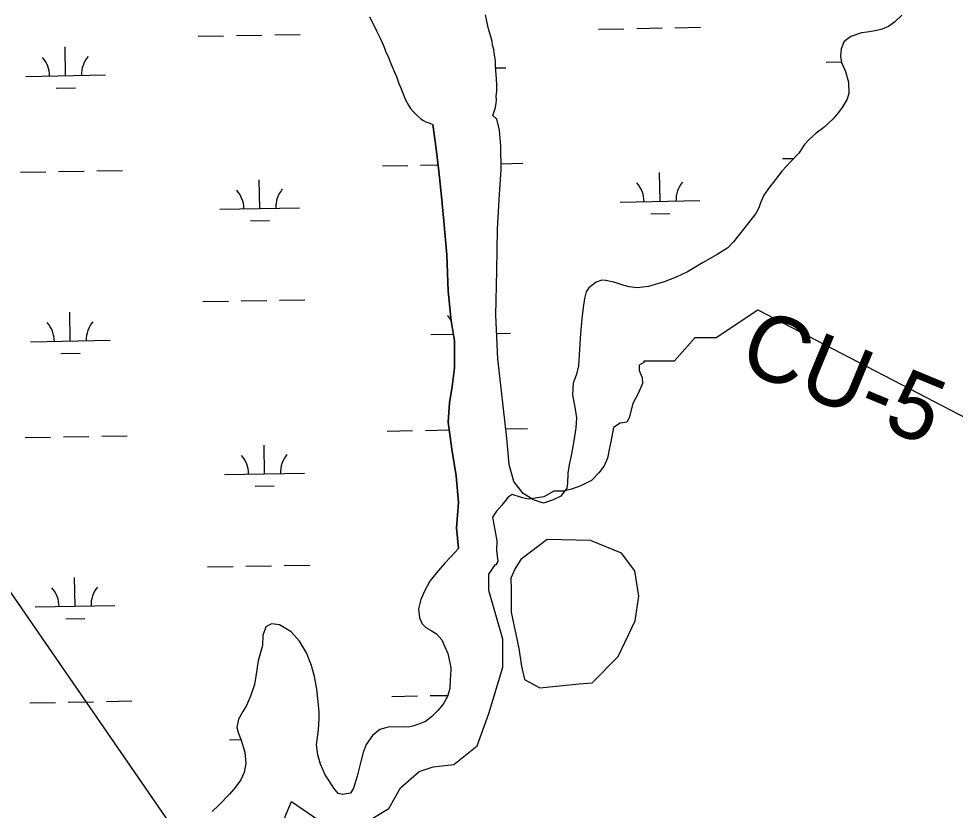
# Model space of a CAD drawing. Extents: x 3914892 to 3953151, y 242587 to 268572.
# Drawn here: x 3940652 to 3941826, y 261355 to 262347 of the extents above; entities that cross this region are included whole.
import ezdxf

# ---------------------------------------------------------------- set-up
doc = ezdxf.new("R2010")
doc.units = 0
for name, color, linetype in [('V-RIVR-EDGE', 7, 'Continuous'), ('V-RIVR-RANG-IDEN', 7, 'Continuous'), ('V-TOPO-SHOR', 7, 'Continuous'), ('V-UTIL-LINE', 7, 'Continuous'), ('V-WETL-SWMP', 7, 'Continuous')]:
    doc.layers.add(name, color=color, linetype=linetype)

msp = doc.modelspace()

# ---------------------------------------------------------------- linework, layer by layer
at = {"layer": 'V-RIVR-EDGE'}
for points in [[(3941436.263321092, 261915.74149882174), (3941436.4269929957, 261918.19657738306), (3941474.2483207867, 261918.19657738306), (3941500.432316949, 261947.2899064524), (3941526.6163131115, 261947.2899064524), (3941578.9843054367, 261982.20190133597), (3943106.3840815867, 261187.95401773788)], [(3941436.0536937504, 261915.87408265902), (3941430.2715205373, 261912.7606047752), (3941430.2715205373, 261906.0888664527), (3941433.8297809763, 261897.19321535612), (3941434.274563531, 261889.6319119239), (3941428.937172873, 261877.17800038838), (3941422.2654345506, 261864.72408885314), (3941417.3728264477, 261846.48800410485), (3941414.7041311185, 261841.15061344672), (3941406.2532625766, 261839.81626578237), (3941397.8023940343, 261834.47887512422), (3941394.688916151, 261816.68757293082), (3941392.9097859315, 261809.12626949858), (3941390.2410906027, 261796.22757540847), (3941386.238047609, 261786.44235920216), (3941379.5663092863, 261777.54670810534), (3941370.225875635, 261768.20627445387), (3941356.88239899, 261761.5345361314), (3941345.3180525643, 261757.08671058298), (3941335.088053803, 261754.8627978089), (3941323.0789248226, 261754.8627978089), (3941310.6250132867, 261747.74627693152), (3941291.4993634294, 261744.63279904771), (3941283.938059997, 261746.41192926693), (3941271.0393659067, 261750.41497226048), (3941265.7019752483, 261747.30149437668), (3941257.6958892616, 261737.0714956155), (3941251.024150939, 261729.51019218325), (3941246.1315428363, 261721.94888875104), (3941251.468933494, 261692.59324013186), (3941251.024150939, 261680.58411115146), (3941252.8032811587, 261666.35106939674), (3941250.5793683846, 261662.3480264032)], [(3941274.787833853, 261657.80073764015), (3941269.083354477, 261645.67871896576), (3941269.796414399, 261631.41752052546), (3941269.796414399, 261602.89512364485), (3941279.066193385, 261557.25928863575), (3941282.631492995, 261535.15443105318), (3941286.1967926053, 261518.75405284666), (3941305.4494105, 261508.0581540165), (3941354.6505451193, 261513.0495734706), (3941371.0509233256, 261514.47569331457), (3941403.8516797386, 261547.27644972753), (3941425.243477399, 261592.19922481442), (3941429.5218369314, 261622.8608014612), (3941424.530417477, 261654.948497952), (3941408.1300392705, 261677.05335553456), (3941368.91174356, 261692.74067381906), (3941314.7191894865, 261694.16679366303), (3941281.9184330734, 261669.2096963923), (3941274.787833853, 261657.75617139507)], [(3940970.9337278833, 261310.14599983), (3940994.2083911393, 261365.42332506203), (3941058.213715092, 261321.78333145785), (3941116.400373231, 261356.69532634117), (3941130.9470377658, 261382.8793225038), (3941154.2217010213, 261403.24465285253), (3941171.6776984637, 261409.06331866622), (3941197.861694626, 261411.9726515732), (3941226.9550236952, 261435.24731482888), (3941241.5016882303, 261475.97797552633), (3941258.9576856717, 261534.16463366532), (3941258.9576856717, 261569.07662854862), (3941241.5016882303, 261630.1726195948), (3941241.5016882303, 261650.5379499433), (3941250.098011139, 261662.81841124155)]]:
    msp.add_lwpolyline(points, dxfattribs=at)
at = {"layer": 'V-TOPO-SHOR'}
for points in [[(3941310.292, 261739.66199999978), (3941297.703, 261744.04499999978), (3941284.72, 261751.65299999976), (3941272.8030000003, 261766.86199999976), (3941267.128, 261788.25099999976), (3941263.98, 261821.34699999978), (3941252.9110000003, 261920.84199999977), (3941250.302, 261975.29299999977), (3941251.676, 262031.51199999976), (3941252.415, 262083.11999999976), (3941254.801, 262126.95699999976), (3941256.88, 262157.54999999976), (3941256.5500000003, 262187.51299999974), (3941254.983, 262207.4379999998), (3941251.754, 262221.3579999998), (3941246.644, 262225.722)], [(3941203.759, 261682.87499999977), (3941201.1580000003, 261708.69999999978), (3941203.454, 261740.65299999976), (3941200.566, 261774.02999999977), (3941195.251, 261807.31199999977), (3941190.715, 261841.43499999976), (3941192.228, 261865.52599999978), (3941195.505, 261885.90399999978), (3941198.389, 261909.50899999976), (3941198.727, 261943.27599999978), (3941194.268, 261968.22099999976), (3941190.418, 262005.61099999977), (3941188.9560000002, 262051.19399999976), (3941185.19, 262093.44599999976), (3941182.404, 262124.12499999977), (3941179.037, 262155.8629999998), (3941175.535, 262184.08399999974), (3941171.576, 262214.5849999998)]]:
    msp.add_lwpolyline(points, dxfattribs=at)
at = {"layer": 'V-UTIL-LINE'}
msp.add_lwpolyline([(3937257.69907959, 266529.8389520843), (3940896.284, 261258.97), (3942305.4820000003, 257189.557), (3945242.894, 251786.949), (3947661.3890917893, 248530.41995604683)], dxfattribs=at)
at = {"layer": 'V-WETL-SWMP'}
for p, q in [((3941238.685, 262346.326), (3941237.545, 262352.113)), ((3941759.256, 262351.529), (3941750.111, 262342.77400000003)), ((3941240.225, 262338.099), (3941238.685, 262346.326)), ((3941241.649, 262332.93700000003), (3941240.225, 262338.099)), ((3941742.523, 262337.288), (3941734.548, 262333.928)), ((3941750.111, 262342.77400000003), (3941742.523, 262337.288)), ((3940877.150642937, 262325.0964673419), (3940909.145522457, 262325.668904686)), ((3940925.142962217, 262325.9551233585), (3940957.137841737, 262326.52756070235)), ((3940973.135281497, 262326.8137793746), (3941005.1301610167, 262327.3862167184)), ((3941244.108, 262324.745), (3941241.649, 262332.93700000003)), ((3941378.978330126, 262334.074932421), (3941410.9732096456, 262334.64736976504)), ((3941426.9706494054, 262334.93358843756), (3941458.965528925, 262335.5060257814)), ((3941474.962968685, 262335.7922444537), (3941506.9578482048, 262336.3646817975)), ((3941708.884, 262329.43700000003), (3941695.461, 262324.646)), ((3941716.035, 262330.32), (3941708.884, 262329.43700000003)), ((3941726.0640000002, 262331.924), (3941716.035, 262330.3199999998)), ((3941734.548, 262333.928), (3941726.0640000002, 262331.924)), ((3941245.578, 262318.356), (3941244.108, 262324.745)), ((3941246.342, 262314.396), (3941245.578, 262318.356)), ((3941247.801, 262308.314), (3941246.342, 262314.396)), ((3941687.291, 262318.374), (3941683.3540000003, 262309.358)), ((3941695.461, 262324.646), (3941687.291, 262318.374)), ((3940710.9439464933, 262275.6853445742), (3940710.2999544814, 262311.6795840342)), ((3941248.235, 262304.955), (3941247.801, 262308.314)), ((3941249.0810000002, 262298.85), (3941248.235, 262304.955)), ((3941683.3540000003, 262309.358), (3941682.322, 262300.3)), ((3941249.869, 262294.277), (3941249.0810000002, 262298.85)), ((3941250.136, 262287.229), (3941249.869, 262294.277)), ((3941664.6073216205, 262292.74784138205), (3941683.573307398, 262293.08717188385)), ((3941682.322, 262300.3), (3941683.6920000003, 262292.403)), ((3941683.6920000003, 262292.403), (3941688.718, 262280.82300000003)), ((3941250.3340000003, 262282.0199999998), (3941250.136, 262287.229)), ((3941250.208046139, 262285.3336043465), (3941262.7636329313, 262285.55824300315)), ((3941251.0360000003, 262271.613), (3941250.3340000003, 262282.0199999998)), ((3941688.718, 262280.82300000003), (3941692.4280000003, 262267.664)), ((3940660.951947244, 262274.7909112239), (3940760.9359457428, 262276.57977792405)), ((3941251.646, 262263.658), (3941251.0360000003, 262271.613)), ((3941692.4280000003, 262267.664), (3941693.114, 262253.626)), ((3940699.221906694, 262260.0421497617), (3940723.218066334, 262260.4714777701)), ((3941250.932, 262250.129), (3941251.619, 262256.292)), ((3941251.619, 262256.292), (3941251.646, 262263.658)), ((3941250.657, 262241.219), (3941251.1070000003, 262245.532)), ((3941251.1070000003, 262245.532), (3941250.932, 262250.129)), ((3941690.9450000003, 262246.359), (3941684.47, 262235.718)), ((3941693.114, 262253.626), (3941690.9450000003, 262246.359)), ((3941247.7290000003, 262229.447), (3941249.935, 262235.975)), ((3941249.935, 262235.975), (3941250.657, 262241.219)), ((3941684.47, 262235.718), (3941679.523, 262229.11)), ((3941246.643, 262225.723), (3941247.7290000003, 262229.447)), ((3941251.754, 262221.357), (3941246.643, 262225.723)), ((3941254.984, 262207.43700000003), (3941251.754, 262221.357)), ((3941673.238, 262221.533), (3941661.426, 262210.537)), ((3941679.523, 262229.11), (3941673.238, 262221.533)), ((3941661.426, 262210.537), (3941651.906, 262203.602)), ((3941256.551, 262187.513), (3941254.984, 262207.43700000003)), ((3941651.906, 262203.602), (3941643.031, 262195.77400000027)), ((3941256.879, 262157.551), (3941256.551, 262187.513)), ((3941637.463, 262189.44800000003), (3941630.389, 262178.478)), ((3941643.031, 262195.77400000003), (3941637.463, 262189.44800000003)), ((3941630.389, 262178.478), (3941620.233, 262168.156)), ((3941108.092640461, 262162.70072607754), (3941140.0875199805, 262163.27316342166)), ((3941156.0849597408, 262163.55938209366), (3941178.0342090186, 262163.952087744)), ((3941256.7935000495, 262165.3612119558), (3941284.0644778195, 262165.84913147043)), ((3941620.233, 262168.156), (3941609.525, 262156.284)), ((3941609.920327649, 262171.67919115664), (3941623.9464435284, 262171.9301398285)), ((3940654.2572725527, 262154.5809170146), (3940686.2521520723, 262155.1533543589)), ((3940702.249591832, 262155.439573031), (3940734.2444713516, 262156.01201037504)), ((3940750.241911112, 262156.29822904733), (3940782.2367906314, 262156.8706663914)), ((3941254.801, 262126.957), (3941256.879, 262157.551)), ((3941456.26077143, 262118.1798658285), (3941455.616779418, 262154.1741052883)), ((3941609.525, 262156.284), (3941601.066, 262145.567)), ((3940954.433084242, 262109.20140074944), (3940953.78909223, 262145.1956402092)), ((3941601.066, 262145.567), (3941593.329, 262135.948)), ((3941252.415, 262083.119), (3941254.801, 262126.957)), ((3941586.379, 262125.748), (3941582.006, 262116.104)), ((3941593.329, 262135.948), (3941586.379, 262125.748)), ((3941406.2687721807, 262117.2854324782), (3941506.2527706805, 262119.0742991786)), ((3941582.006, 262116.104), (3941580.248, 262110.07499999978)), ((3940904.4410849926, 262108.3069673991), (3941004.425083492, 262110.09583409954)), ((3941444.538731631, 262102.536671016), (3941468.5348912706, 262102.9659990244)), ((3941576.552, 262102.74999999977), (3941567.211, 262091.083)), ((3941580.248, 262110.07499999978), (3941576.552, 262102.74999999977)), ((3940942.7110444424, 262093.55820593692), (3940966.707204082, 262093.98753394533)), ((3941567.211, 262091.083), (3941548.237, 262067.432)), ((3941251.6750000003, 262031.513), (3941252.415, 262083.119)), ((3941548.237, 262067.432), (3941541.183, 262059.979)), ((3941541.183, 262059.979), (3941527.898, 262051.525)), ((3941527.898, 262051.525), (3941509.494, 262041.043)), ((3941509.494, 262041.043), (3941490.807, 262029.93800000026)), ((3941250.301, 261975.29200000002), (3941251.6750000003, 262031.513)), ((3941476.3910000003, 262023.122), (3941461.323, 262017.352)), ((3941490.807, 262029.938), (3941476.3910000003, 262023.12199999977)), ((3941367.1380000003, 262009.80000000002), (3941363.824, 262004.476)), ((3941376.2, 262016.717), (3941367.1380000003, 262009.80000000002)), ((3941383.44, 262019.285), (3941376.2, 262016.717)), ((3941388.1890000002, 262019.007), (3941383.44, 262019.285)), ((3941394.201, 262017.707), (3941388.1890000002, 262019.00699999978)), ((3941398.21, 262016.78900000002), (3941394.201, 262017.70700000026)), ((3941402.39, 262015.419), (3941398.21, 262016.78899999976)), ((3941408.271, 262013.502), (3941402.39, 262015.419)), ((3941417.687, 262011.108), (3941408.271, 262013.502)), ((3941427.3740000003, 262009.642), (3941417.687, 262011.108)), ((3941441.9820000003, 262011.42), (3941427.3740000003, 262009.64199999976)), ((3941461.323, 262017.352), (3941441.9820000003, 262011.42)), ((3941363.824, 262004.476), (3941361.5360000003, 261996.287)), ((3940883.101755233, 261992.47470033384), (3940915.0966347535, 261993.0471376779)), ((3940931.0940745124, 261993.33335635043), (3940963.088954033, 261993.90579369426)), ((3940979.0863937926, 261994.19201236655), (3941011.0812733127, 261994.76444971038)), ((3941359.67, 261985.057), (3941358.078, 261970.62699999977)), ((3941361.5360000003, 261996.287), (3941359.67, 261985.057)), ((3940716.8950587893, 261943.06357756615), (3940716.2510667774, 261979.05781702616)), ((3941252.91, 261920.842), (3941250.301, 261975.29200000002)), ((3941358.078, 261970.62699999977), (3941356.473, 261952.527)), ((3941168.730746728, 261951.1476092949), (3941197.2291175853, 261951.6574887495)), ((3941251.387031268, 261952.62645668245), (3941268.714745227, 261952.93647599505)), ((3941356.473, 261952.527), (3941355.242, 261932.608)), ((3940666.90305954, 261942.16914421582), (3940766.8870580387, 261943.958010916)), ((3940705.1730189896, 261927.42038275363), (3940729.1691786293, 261927.84971076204)), ((3941355.242, 261932.608), (3941354.046, 261911.772)), ((3941263.981, 261821.34600000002), (3941252.91, 261920.842)), ((3941354.046, 261911.772), (3941351.3880000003, 261901.276)), ((3941351.3880000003, 261901.276), (3941347.531, 261890.123)), ((3941347.531, 261890.123), (3941346.397, 261875.71)), ((3941346.397, 261875.71), (3941349.682, 261857.644)), ((3941349.682, 261857.644), (3941351.4790000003, 261846.553)), ((3941351.4790000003, 261846.553), (3941350.5810000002, 261833.984)), ((3941262.7133045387, 261832.7388848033), (3941290.0155901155, 261833.2273644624)), ((3941350.5810000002, 261833.984), (3941348.137, 261817.839)), ((3940660.208384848, 261821.95915000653), (3940692.203264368, 261822.53158735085)), ((3940708.200704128, 261822.81780602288), (3940740.1955836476, 261823.39024336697)), ((3940756.1930234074, 261823.67646203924), (3940788.1879029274, 261824.24889938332)), ((3941114.043752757, 261830.0789590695), (3941146.0386322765, 261830.65139641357)), ((3941162.0360720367, 261830.9376150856), (3941192.0383628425, 261831.47440196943)), ((3941267.128, 261788.25), (3941263.981, 261821.34600000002)), ((3940960.384196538, 261776.57963374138), (3940959.7402045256, 261812.57387320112)), ((3941348.137, 261817.839), (3941345.241, 261801.525)), ((3941345.241, 261801.525), (3941342.252, 261787.654)), ((3941272.802, 261766.862), (3941267.128, 261788.25)), ((3941342.252, 261787.654), (3941340.503, 261777.345)), ((3940910.392197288, 261775.68520039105), (3941010.3761957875, 261777.47406709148)), ((3941340.503, 261777.345), (3941340.075, 261764.488)), ((3941284.721, 261751.653), (3941272.802, 261766.862)), ((3941340.075, 261764.488), (3941339.379, 261758.652)), ((3940948.6621567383, 261760.93643892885), (3940972.6583163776, 261761.36576693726)), ((3941297.702, 261744.045), (3941284.721, 261751.65299999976)), ((3941339.379, 261758.652), (3941331.6720000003, 261748.27000000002)), ((3941310.291, 261739.662), (3941297.702, 261744.045)), ((3941321.6070000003, 261743.608), (3941310.291, 261739.662)), ((3941331.6720000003, 261748.27000000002), (3941321.6070000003, 261743.60799999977)), ((3940889.052867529, 261659.852933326), (3940921.0477470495, 261660.4253706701)), ((3940937.045186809, 261660.7115893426), (3940969.040066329, 261661.28402668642)), ((3940985.037506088, 261661.57024535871), (3941017.032385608, 261662.14268270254)), ((3940722.846171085, 261610.44181055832), (3940722.202179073, 261646.43605001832)), ((3940672.8541718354, 261609.547377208), (3940772.8381703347, 261611.33624390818)), ((3940711.1241312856, 261594.7986157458), (3940735.1202909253, 261595.2279437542)), ((3940762.1441357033, 261491.0546950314), (3940794.139015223, 261491.6271323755)), ((3941119.9948650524, 261497.45719206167), (3941151.989744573, 261498.02962940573)), ((3941167.9871843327, 261498.3158480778), (3941190.2266863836, 261498.71374679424)), ((3940666.1594971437, 261489.3373829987), (3940698.1543766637, 261489.90982034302)), ((3940714.1518164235, 261490.19603901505), (3940746.1466959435, 261490.76847635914)), ((3940916.3433095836, 261443.06343338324), (3940930.667007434, 261443.31970625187))]:
    msp.add_line(p, q, dxfattribs=at)
for points in [[(3941092.1950000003, 262349.353), (3941095.8340000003, 262342.433), (3941100.8370000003, 262331.88300000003), (3941105.17, 262322.842), (3941107.843, 262317.113), (3941110.2090000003, 262311.37200000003), (3941112.245, 262306.233), (3941115.612, 262298.382), (3941118.649, 262291.13300000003), (3941123.359, 262280.265), (3941125.713, 262274.831), (3941128.8200000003, 262265.743), (3941131.5160000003, 262259.401), (3941133.882, 262253.66000000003), (3941137.261, 262245.503), (3941140.899, 262238.58400000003), (3941143.1950000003, 262234.68200000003), (3941147.365, 262229.93), (3941151.5, 262226.098), (3941156.271, 262221.676), (3941159.723, 262219.659), (3941162.551, 262217.926), (3941167.535, 262215.967), (3941171.577, 262214.586), (3941175.5360000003, 262184.08400000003), (3941179.038, 262155.863), (3941182.4050000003, 262124.125), (3941185.19, 262093.446), (3941188.9560000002, 262051.193), (3941190.418, 262005.611), (3941194.269, 261968.22100000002), (3941198.727, 261943.276), (3941198.389, 261909.508), (3941195.506, 261885.904), (3941192.2290000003, 261865.527), (3941190.714, 261841.435), (3941195.251, 261807.312), (3941200.566, 261774.029), (3941203.454, 261740.653), (3941201.1580000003, 261708.7), (3941203.759, 261682.875), (3941193.762, 261672.40600000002), (3941186.126, 261664.16700000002), (3941175.876, 261652.312), (3941167.552, 261642.059), (3941160.853, 261629.27000000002), (3941156.198, 261619.00400000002), (3941153.592, 261607.134), (3941154.4790000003, 261595.855), (3941157.969, 261588.497), (3941162.5870000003, 261583.628), (3941169.296, 261580.06100000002), (3941175.875, 261575.878), (3941182.881, 261568.50100000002), (3941186.588, 261559.469), (3941190.112, 261551.196), (3941194.137, 261533.769), (3941193.778, 261531.15600000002), (3941193.2260000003, 261517.53), (3941192.546, 261507.26200000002), (3941189.864, 261497.377), (3941184.423, 261487.692), (3941177.849, 261479.646), (3941169.896, 261471.7), (3941162.3140000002, 261466.062), (3941154.792, 261462.872), (3941147.705, 261460.309), (3941141.029, 261458.986), (3941134.295, 261459.188), (3941115.349, 261458.927), (3941104.921, 261455.779), (3941095.576, 261448.24000000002), (3941087.898, 261437.094), (3941083.848, 261427.00400000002), (3941080.525, 261413.884), (3941076.419, 261397.218), (3941071.7800000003, 261382.519), (3941068.207, 261375.96300000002), (3941058.332, 261374.36500000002), (3941052.778, 261375.68300000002), (3941047.327, 261382.355), (3941041.478, 261391.458), (3941036.45, 261399.063), (3941030.433, 261412.592), (3941027.25, 261423.937)], [(3941027.25, 261423.937), (3941025.395, 261436.554), (3941027.8880000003, 261455.45200000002), (3941029.068, 261468.643), (3941028.873, 261477.80800000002), (3941027.458, 261490.901), (3941025.804, 261506.278), (3941023.205, 261522.383), (3941019.465, 261536.305), (3941012.909, 261551.954), (3941004.256, 261566.453), (3940993.718, 261578.282), (3940979.3140000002, 261587.21300000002), (3940969.029, 261588.351), (3940961.994, 261584.415), (3940958.431, 261573.579), (3940957.826, 261561.326), (3940952.4450000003, 261542.013), (3940949.719, 261525.247), (3940947.617, 261512.174), (3940942.978, 261497.475), (3940937.906, 261486.123), (3940933.153, 261478.45200000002), (3940927.559, 261468.761), (3940925.6580000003, 261458.44700000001), (3940927.275, 261452.08800000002), (3940931.005, 261442.446), (3940935.7, 261427.49000000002), (3940936.856, 261413.165), (3940934.995, 261401.782), (3940930.758, 261392.602), (3940924.0670000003, 261383.634), (3940916.612, 261374.63700000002), (3940902.921, 261360.817), (3940894.651, 261353.166)]]:
    msp.add_lwpolyline(points, dxfattribs=at)
for centre, radius, start, end in [((3941659.35673087, 262293.12877945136), 35.24628790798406, 40.32661665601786, 41.79683806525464), ((3940655.701356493, 262275.1718492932), 35.24628790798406, 0.25317973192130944, 41.79683806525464), ((3940766.169549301, 262277.1482942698), 35.24628790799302, 140.25317672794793, 181.79683506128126), ((3941401.018181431, 262117.66637054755), 35.24628790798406, 0.25317973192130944, 41.79683806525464), ((3941511.486374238, 262119.6428155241), 35.24628790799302, 140.25317672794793, 181.79683506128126), ((3940899.190494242, 262108.68790546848), 35.24628790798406, 0.25317973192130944, 41.79683806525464), ((3941009.6586870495, 262110.66435044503), 35.24628790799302, 140.25317672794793, 181.79683506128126), ((3941163.4801559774, 261951.52854736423), 35.24628790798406, 29.323072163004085, 41.79683806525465), ((3940661.6524687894, 261942.55008228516), 35.24628790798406, 0.25317973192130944, 41.79683806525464), ((3940772.1206615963, 261944.52652726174), 35.24628790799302, 140.25317672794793, 181.79683506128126), ((3940905.141606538, 261776.06613846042), 35.24628790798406, 0.25317973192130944, 41.79683806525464), ((3941015.609799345, 261778.04258343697), 35.24628790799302, 140.25317672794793, 181.79683506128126), ((3940667.603581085, 261609.92831527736), 35.24628790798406, 0.25317973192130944, 41.79683806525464), ((3940778.0717738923, 261611.9047602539), 35.24628790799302, 140.25317672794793, 181.79683506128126)]:
    msp.add_arc(centre, radius, start, end, dxfattribs=at)

# ---------------------------------------------------------------- texts
at = {"layer": 'V-RIVR-RANG-IDEN'}
msp.add_text('CU-5  ', height=82.99999800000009, rotation=337.4724742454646, dxfattribs=at).set_placement((3941551.1269180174, 261909.9368517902))

doc.saveas('drawing.dxf')
